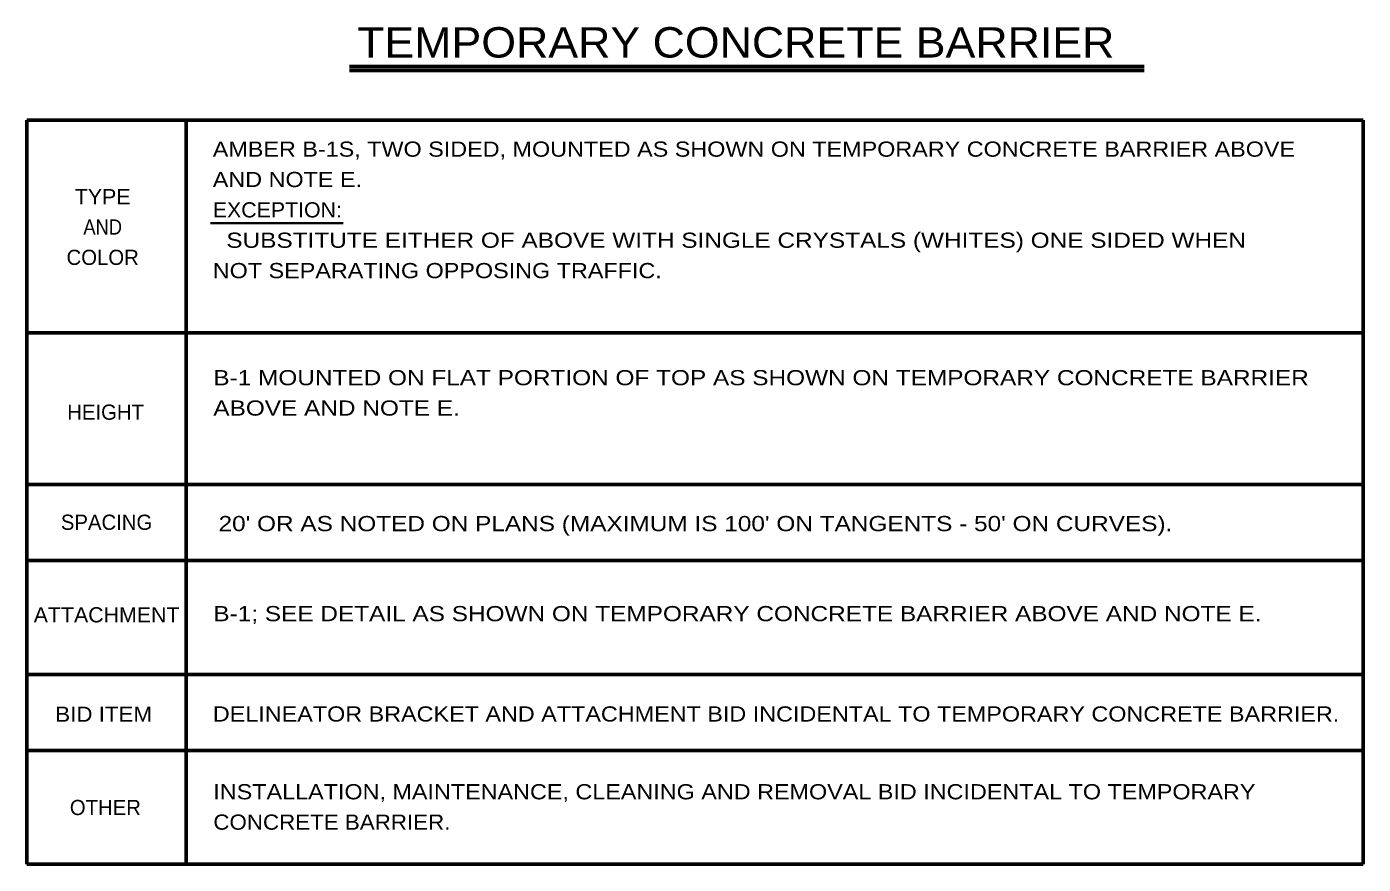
# Model space of a CAD drawing. Extents: x -60 to 620, y -42 to 398.
# Drawn here: x 158 to 334, y 162.5 to 272.9 of the extents above; entities that cross this region are included whole.
import ezdxf
from ezdxf.enums import TextEntityAlignment as Align

# ---------------------------------------------------------------- set-up
doc = ezdxf.new("R2010")
doc.units = 0
doc.header["$LTSCALE"] = 0.8
doc.layers.add('1', color=7, linetype='Continuous', lineweight=35)

msp = doc.modelspace()

# ---------------------------------------------------------------- linework, layer by layer
at = {"layer": '1', "lineweight": 53}
for p, q in [((200.5072, 267.6088), (305.1696, 267.6088)), ((200.5072, 267.1088), (305.1696, 267.1088)), ((158.0131, 260.5388), (334.0131, 260.5388)), ((158.0131, 260.5388), (158.0131, 162.5388)), ((179.0131, 260.5388), (179.0131, 162.5388)), ((334.0131, 260.5388), (334.0131, 162.5388)), ((158.0131, 232.5388), (334.0131, 232.5388)), ((158.0131, 212.5388), (334.0131, 212.5388)), ((158.0131, 202.5388), (334.0131, 202.5388)), ((158.0131, 187.5388), (334.0131, 187.5388)), ((158.0131, 177.5388), (334.0131, 177.5388)), ((158.0131, 162.5388), (334.0131, 162.5388))]:
    msp.add_line(p, q, dxfattribs=at)
at = {"layer": '1'}
msp.add_line((182.1907, 247.001), (199.6933, 247.001), dxfattribs=at)

# ---------------------------------------------------------------- texts
for s, height, width, p in [('TEMPORARY CONCRETE BARRIER', 4, 1.1, (201.5278, 268.7933)), ('AMBER B-1S, TWO SIDED, MOUNTED AS SHOWN ON TEMPORARY CONCRETE BARRIER ABOVE', 2, 1.15, (182.5132, 255.7333)), ('AND NOTE E.', 2, 1.15, (182.5132, 251.7333)), ('EXCEPTION:', 2, 1.05, (182.5132, 247.7333)), ('  SUBSTITUTE EITHER OF ABOVE WITH SINGLE CRYSTALS (WHITES) ONE SIDED WHEN', 2, 1.2, (182.5132, 243.7333)), ('NOT SEPARATING OPPOSING TRAFFIC.', 2, 1.15, (182.5132, 239.7333)), ('B-1 MOUNTED ON FLAT PORTION OF TOP AS SHOWN ON TEMPORARY CONCRETE BARRIER', 2, 1.2, (182.5854, 225.6298)), ('ABOVE AND NOTE E.', 2, 1.2, (182.5854, 221.6298)), ('B-1; SEE DETAIL AS SHOWN ON TEMPORARY CONCRETE BARRIER ABOVE AND NOTE E.', 2, 1.2, (182.5854, 194.5511)), ('INSTALLATION, MAINTENANCE, CLEANING AND REMOVAL BID INCIDENTAL TO TEMPORARY', 2, 1.15, (182.5854, 171.0915)), ('CONCRETE BARRIER.', 2, 1.1, (182.5854, 167.0915))]:
    msp.add_text(s, height=height, dxfattribs=dict(at, width=width)).set_placement(p)
for s, width, p in [('TYPE', 1.05, (168.0147, 249.476)), ('AND', 0.9, (168.0147, 245.476)), ("20' OR AS NOTED ON PLANS (MAXIMUM IS 100' ON TANGENTS - 50' ON CURVES).", 1.2, (246.071, 206.4125)), ('ATTACHMENT', 1.05, (168.5279, 194.3955)), ('BID ITEM', 1.1, (168.1429, 181.3046)), ('DELINEATOR BRACKET AND ATTACHMENT BID INCIDENTAL TO TEMPORARY CONCRETE BARRIER.', 1.15, (256.6895, 181.3378))]:
    msp.add_text(s, height=2, dxfattribs=dict(at, width=width)).set_placement(p, align=Align.CENTER)
for s, p in [('COLOR', (168.0146, 241.476)), ('HEIGHT', (168.3995, 221.0908)), ('SPACING', (168.5279, 206.5881)), ('OTHER', (168.368, 169.0183))]:
    msp.add_text(s, height=2, dxfattribs=at).set_placement(p, align=Align.CENTER)

doc.saveas('drawing.dxf')
